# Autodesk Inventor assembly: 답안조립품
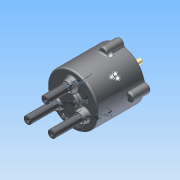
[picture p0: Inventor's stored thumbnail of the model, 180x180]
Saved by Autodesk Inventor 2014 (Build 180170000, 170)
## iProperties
Created: 2015-09
Part Number: 답안조립품
Document SubType Name: Assembly
Designer: study
Mass: 2160.26 g
Surface Area: 1801.22 cm^2
Volume: 438.524 cm^3
Density: 4.9262 g/cm^3
Author: study
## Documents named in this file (14)
- C:\Users\study\Desktop\350916V1015\답안조립품.iam
- C:\Users\study\Desktop\350916V1015\몸체.ipt
- C:\Users\study\Desktop\350916V1015\M5x0.8x20.ipt
- C:\Users\study\Desktop\350916V1015\커버.ipt
- C:\Users\study\Desktop\350916V1015\오일실.ipt
- C:\Users\study\Desktop\350916V1015\베어링 NA 4900.ipt
- C:\Users\study\Desktop\350916V1015\메인 축.ipt
- C:\Users\study\Desktop\350916V1015\멈춤링 10 x 1.ipt
- C:\Users\study\Desktop\350916V1015\멈춤링 22 x 1.2.ipt
- C:\Users\study\Desktop\350916V1015\판캠.ipt
- C:\Users\study\Desktop\350916V1015\슬라이드 축.ipt
- C:\Users\study\Desktop\350916V1015\11가변 스프링.ipt
- C:\Users\study\Desktop\350916V1015\12가변 스프링.ipt
- C:\Users\study\Desktop\350916V1015\13가변 스프링.ipt
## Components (7 placed, 4 different names)
1. 11가변 스프링:1
2. 12가변 스프링:1
3. 13가변 스프링:1
4. M5x0.8x20:1
5. M5x0.8x20:2
6. M5x0.8x20:3
7. M5x0.8x20:4
